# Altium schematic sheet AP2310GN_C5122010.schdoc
size 127 x 101 mm
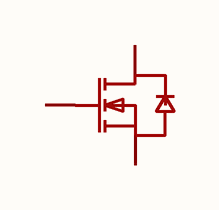
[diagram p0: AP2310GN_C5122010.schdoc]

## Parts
Q?  ap2310gn  [SOT-23-3_L2.9-W1.3-P1.90-LS2.4-BR]  (value not drawn)

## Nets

Not connected (* = marked no-connect by the designer): Q? 1(G) 2(S) 3(D)

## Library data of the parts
Q? = ap2310gn: 数量:1个N沟道;漏源电压(Vdss):60V;连续漏极电流(Id):3A;导通电阻(RDS(on)):125mΩ@4.5V;耗散功率(Pd):350mW;阈值电压(Vgs(th)):500mV;; Manufacturer: TECH PUBLIC(台舟); Symbol: AP2310GN_C5122010; AddInBom: yes; ModelId: c62791f0466c4ae2a892c056b845b0ca; ModelName: SOT-23-3P_L2.9-W1.3-H1.0-LS2.4-P0.95; ModelTransform: 98.425,114.173,0,180,0,0,0.0005,-0.0005,0; Number: 1个N沟道; Drain to Source Voltage: 60V; Current - Continuous Drain(Id): 3A; Pd - Power Dissipation: 350mW; Gate Threshold Voltage (Vgs(th)): 500mV; Gate Charge(Qg): 6nC; Input Capacitance(Ciss): 247pF; Reverse Transfer Capacitance (Crss@Vds): 19.5pF; Type: N沟道; Output Capacitance(Coss): 34pF; Vgs: ±20V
